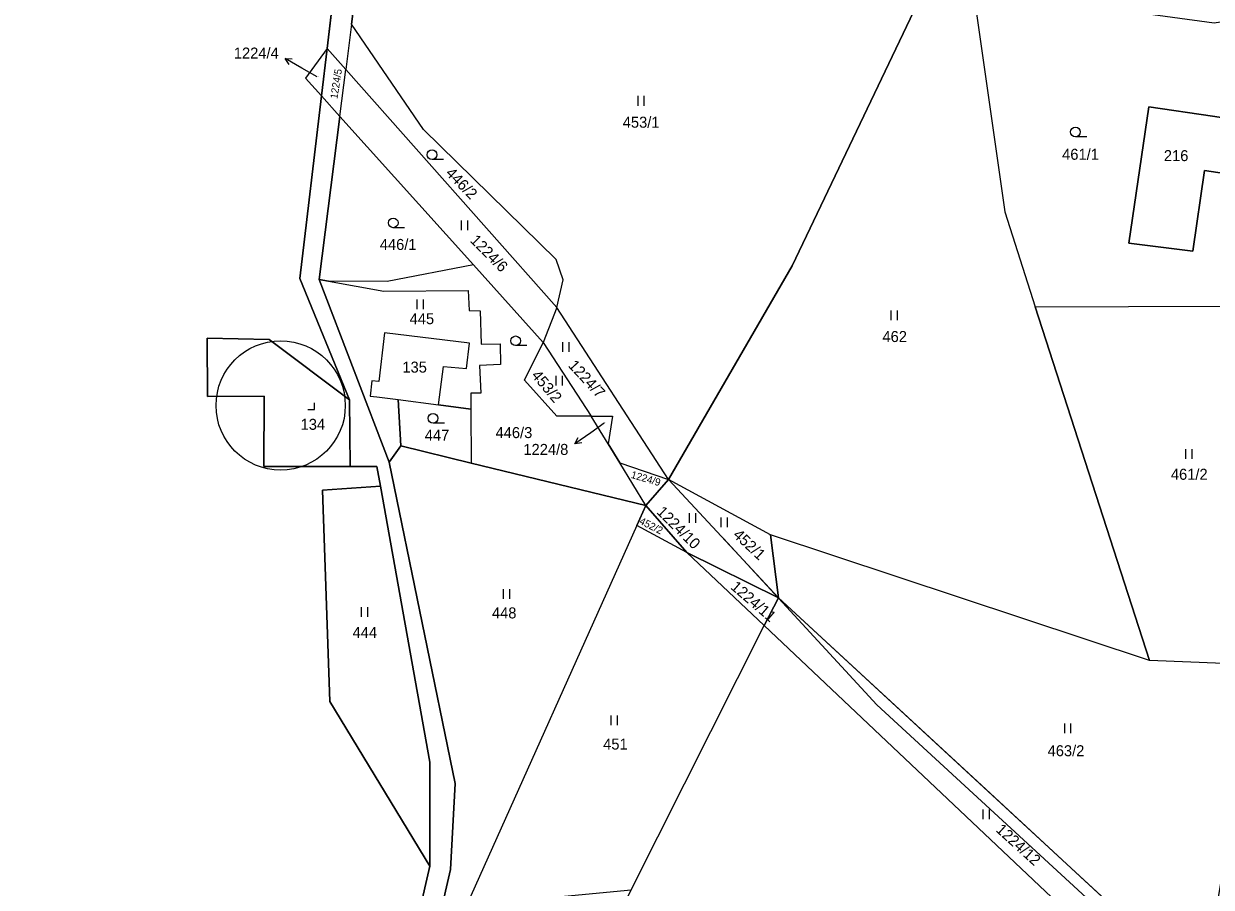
# Model space of a CAD drawing. Extents: x -588699 to -585793, y -1060280 to -1056731.
# Drawn here: x -587129.7 to -586946, y -1058770.6 to -1058637 of the extents above; entities that cross this region are included whole.
import ezdxf

# ---------------------------------------------------------------- set-up
doc = ezdxf.new("R2010")
doc.units = 0
for name, color, linetype in [('Druh pozemku', 7, 'Continuous'), ('Lesy', 7, 'Continuous'), ('Parcela nároku', 7, 'Continuous'), ('Parcelní číslo', 7, 'Continuous'), ('Stavby', 7, 'Continuous'), ('Vnější obvod_k šeření', 7, 'Continuous')]:
    doc.layers.add(name, color=color, linetype=linetype)

msp = doc.modelspace()

# ---------------------------------------------------------------- linework, layer by layer
at = {"layer": 'Druh pozemku'}
for p, q in [((-587034.74, -1058648.17), (-587034.74, -1058649.67)), ((-587033.71, -1058649.67), (-587033.71, -1058648.17)), ((-586965.26, -1058654.48), (-586967.01, -1058654.48)), ((-587064.8, -1058658), (-587066.55, -1058658)), ((-587062.05, -1058667.43), (-587062.05, -1058668.93)), ((-587061.03, -1058668.93), (-587061.03, -1058667.43)), ((-587070.81, -1058668.55), (-587072.56, -1058668.55)), ((-587068.92, -1058679.65), (-587068.92, -1058681.15)), ((-587067.9, -1058681.15), (-587067.9, -1058679.65)), ((-586995.56, -1058681.38), (-586995.56, -1058682.88)), ((-586994.54, -1058682.88), (-586994.54, -1058681.38)), ((-587051.87, -1058686.8), (-587053.62, -1058686.8)), ((-587046.36, -1058686.24), (-587046.36, -1058687.74)), ((-587045.33, -1058687.74), (-587045.33, -1058686.24)), ((-587047.38, -1058691.46), (-587047.38, -1058692.96)), ((-587046.35, -1058692.96), (-587046.35, -1058691.46)), ((-587064.65, -1058698.79), (-587066.4, -1058698.79)), ((-586949.96, -1058702.82), (-586949.96, -1058704.32)), ((-586948.94, -1058704.32), (-586948.94, -1058702.82)), ((-587026.78, -1058712.69), (-587026.78, -1058714.19)), ((-587025.76, -1058714.19), (-587025.76, -1058712.69)), ((-587021.87, -1058713.38), (-587021.87, -1058714.88)), ((-587020.84, -1058714.88), (-587020.84, -1058713.38)), ((-587055.54, -1058724.49), (-587055.54, -1058725.99)), ((-587054.52, -1058725.99), (-587054.52, -1058724.49)), ((-587077.52, -1058727.27), (-587077.52, -1058728.77)), ((-587076.49, -1058728.77), (-587076.49, -1058727.27)), ((-587038.9, -1058744.02), (-587038.9, -1058745.52)), ((-587037.88, -1058745.52), (-587037.88, -1058744.02)), ((-586968.72, -1058745.27), (-586968.72, -1058746.77)), ((-586967.7, -1058746.77), (-586967.7, -1058745.27)), ((-586981.34, -1058758.54), (-586981.34, -1058760.04)), ((-586980.32, -1058760.04), (-586980.32, -1058758.54))]:
    msp.add_line(p, q, dxfattribs=at)
msp.add_lwpolyline([(-587085.76, -1058696.66), (-587084.76, -1058696.66), (-587084.76, -1058695.66)], dxfattribs=at)
for centre in [(-586967.01, -1058653.73), (-587066.55, -1058657.25), (-587072.56, -1058667.8), (-587053.62, -1058686.05), (-587066.4, -1058698.04)]:
    msp.add_circle(centre, 0.75, dxfattribs=at)
at = {"layer": 'Lesy'}
for p, q in [((-587082.77, -1058640.81), (-587081.62, -1058631.18)), ((-587079.89, -1058644.06), (-587082.77, -1058640.81)), ((-587080.81, -1058651.32), (-587079.89, -1058644.06)), ((-587084.01, -1058676.54), (-587080.81, -1058651.32)), ((-587073.2, -1058704.82), (-587084.01, -1058676.54)), ((-587071.38, -1058702.32), (-587073.2, -1058704.82)), ((-587060.49, -1058704.96), (-587071.38, -1058702.32)), ((-587033.48, -1058711.51), (-587060.49, -1058704.96)), ((-587029.95, -1058707.51), (-587033.48, -1058711.51)), ((-587012.97, -1058725.79), (-587029.95, -1058707.51)), ((-586980.88, -1058755.42), (-587012.97, -1058725.79)), ((-586948.79, -1058785.05), (-586980.88, -1058755.42))]:
    msp.add_line(p, q, dxfattribs=at)
at = {"layer": 'Parcela nároku'}
for points in [[(-587082.77, -1058640.81), (-587081.62, -1058631.18), (-587082.04, -1058616.39), (-587089.34, -1058602.34), (-587092.39, -1058597.59), (-587095.99, -1058591.99), (-587093.17, -1058592.2), (-587086.6, -1058600.68), (-587081.74, -1058610.11), (-587078.73, -1058615.94), (-587078.34, -1058619.18), (-587077.6, -1058628.08), (-587078.23, -1058630.94), (-587079.01, -1058637.07), (-587079.89, -1058644.06)], [(-587079.01, -1058637.07), (-587078.23, -1058630.94), (-587027.45, -1058629.2), (-586988.17, -1058626.9), (-587010.84, -1058674.44), (-587029.95, -1058707.51), (-587047.27, -1058680.89), (-587046.25, -1058676.64), (-587047.36, -1058673.49), (-587067.87, -1058653.34)], [(-586988.17, -1058626.9), (-586973.23, -1058633.1), (-586982.68, -1058632.84), (-586977.96, -1058666.11), (-586973.22, -1058680.8), (-586955.56, -1058735.53), (-587014.17, -1058716.09), (-587029.95, -1058707.51), (-587010.84, -1058674.44)], [(-586932.16, -1058655.81), (-586936.67, -1058654.08), (-586933.73, -1058645.96), (-586930.55, -1058647.2), (-586927.38, -1058634.01), (-586945.54, -1058636.92), (-586973.23, -1058633.1), (-586982.68, -1058632.84), (-586977.96, -1058666.11), (-586973.22, -1058680.8), (-586929.95, -1058680.64), (-586929.59, -1058679.33), (-586933.94, -1058678.03)], [(-587067.87, -1058653.34), (-587079.01, -1058637.07), (-587079.89, -1058644.06), (-587047.27, -1058680.89), (-587046.25, -1058676.64), (-587047.36, -1058673.49)], [(-587082.77, -1058640.81), (-587086.11, -1058645.42), (-587083.65, -1058648.16)], [(-587079.89, -1058644.06), (-587082.77, -1058640.81), (-587083.65, -1058648.16), (-587080.81, -1058651.32)], [(-587080.81, -1058651.32), (-587079.89, -1058644.06), (-587047.27, -1058680.89), (-587049.34, -1058686.33), (-587060.15, -1058674.31)], [(-586945.81, -1058651.29), (-586941.68, -1058651.91), (-586942.92, -1058660.31), (-586947.04, -1058659.71), (-586948.86, -1058672.19), (-586958.77, -1058670.94), (-586955.67, -1058649.84)], [(-586958.77, -1058670.94), (-586948.86, -1058672.19), (-586947.04, -1058659.71), (-586942.92, -1058660.31), (-586941.68, -1058651.91), (-586945.81, -1058651.29), (-586955.67, -1058649.84)], [(-587080.81, -1058651.32), (-587060.15, -1058674.31), (-587073.49, -1058676.85), (-587082.55, -1058676.8), (-587084.01, -1058676.54)], [(-587073.49, -1058676.85), (-587082.55, -1058676.8), (-587074, -1058678.35), (-587060.98, -1058678.24), (-587060.81, -1058681.36), (-587059.09, -1058681.39), (-587058.97, -1058686.57), (-587056.02, -1058686.51), (-587055.96, -1058689.7), (-587059.21, -1058689.85), (-587058.98, -1058694.14), (-587060.57, -1058694.14), (-587060.55, -1058696.65), (-587060.49, -1058704.96), (-587033.48, -1058711.51), (-587037.52, -1058704.92), (-587039.31, -1058702), (-587041.95, -1058697.7), (-587047.24, -1058697.69), (-587052.26, -1058692.13), (-587049.34, -1058686.33), (-587060.15, -1058674.31)], [(-587075.07, -1058694.71), (-587071.77, -1058695.15), (-587071.38, -1058702.32), (-587073.2, -1058704.82), (-587084.01, -1058676.54), (-587082.55, -1058676.8), (-587074, -1058678.35), (-587060.98, -1058678.24), (-587060.81, -1058681.36), (-587059.09, -1058681.39), (-587058.97, -1058686.57), (-587056.02, -1058686.51), (-587055.96, -1058689.7), (-587059.21, -1058689.85), (-587058.98, -1058694.14), (-587060.57, -1058694.14), (-587060.55, -1058696.65), (-587065.54, -1058695.97), (-587064.79, -1058690), (-587061.24, -1058690.33), (-587060.77, -1058686.4), (-587073.89, -1058684.82), (-587074.8, -1058692.36), (-587075.86, -1058692.23), (-587076.15, -1058694.63)], [(-587029.95, -1058707.51), (-587047.27, -1058680.89), (-587049.34, -1058686.33), (-587041.95, -1058697.7), (-587038.65, -1058697.7), (-587039.31, -1058702), (-587037.52, -1058704.92)], [(-586973.22, -1058680.8), (-586929.95, -1058680.64), (-586935.97, -1058702.25), (-586938.93, -1058736.17), (-586955.56, -1058735.53)], [(-587091.76, -1058685.84), (-587079.33, -1058695.16), (-587079.21, -1058705.5), (-587092.6, -1058705.5), (-587092.52, -1058694.6), (-587101.31, -1058694.64), (-587101.33, -1058685.65)], [(-587073.89, -1058684.82), (-587074.8, -1058692.36), (-587075.86, -1058692.23), (-587076.15, -1058694.63), (-587075.07, -1058694.71), (-587071.77, -1058695.15), (-587065.54, -1058695.97), (-587064.79, -1058690), (-587061.24, -1058690.33), (-587060.77, -1058686.4)], [(-587049.34, -1058686.33), (-587041.95, -1058697.7), (-587047.24, -1058697.69), (-587052.26, -1058692.13)], [(-587065.54, -1058695.97), (-587060.55, -1058696.65), (-587060.49, -1058704.96), (-587071.38, -1058702.32), (-587071.77, -1058695.15)], [(-587041.95, -1058697.7), (-587038.65, -1058697.7), (-587039.31, -1058702)], [(-587068.95, -1058790.69), (-587063.69, -1058767.86), (-587062.95, -1058754.55), (-587073.2, -1058704.82), (-587071.38, -1058702.32), (-587060.49, -1058704.96), (-587033.48, -1058711.51), (-587034.88, -1058714.63), (-587061.22, -1058773.43)], [(-587037.52, -1058704.92), (-587029.95, -1058707.51), (-587033.48, -1058711.51)], [(-587033.48, -1058711.51), (-587029.95, -1058707.51), (-587012.97, -1058725.79), (-587027.13, -1058718.82)], [(-587012.97, -1058725.79), (-587014.17, -1058716.09), (-587029.95, -1058707.51)], [(-587074.55, -1058708.53), (-587066.87, -1058751.26), (-587066.87, -1058767.35), (-587082.35, -1058741.85), (-587083.48, -1058709.16)], [(-587034.88, -1058714.63), (-587033.48, -1058711.51), (-587027.13, -1058718.82)], [(-587027.13, -1058718.82), (-587034.88, -1058714.63), (-587061.22, -1058773.43), (-587035.75, -1058770.98), (-587015.18, -1058730.11)], [(-586955.56, -1058735.53), (-587014.17, -1058716.09), (-587012.97, -1058725.79), (-586948.79, -1058785.05), (-586945.33, -1058774.96), (-586938.93, -1058736.17)], [(-587027.13, -1058718.82), (-587012.97, -1058725.79), (-587015.18, -1058730.11)], [(-587012.97, -1058725.79), (-586948.79, -1058785.05), (-586950.81, -1058790.94), (-587015.18, -1058730.11)], [(-587049, -1058798.36), (-587035.75, -1058770.98), (-587015.18, -1058730.11), (-586950.81, -1058790.94), (-586952.1, -1058794.64), (-586956.26, -1058799.45), (-586977.77, -1058790.14), (-586983.47, -1058791.82), (-586986.93, -1058805.34), (-586975.35, -1058815.6), (-587001.81, -1058846.94), (-587015.61, -1058862.01), (-587018.01, -1058859.21), (-587014.91, -1058836.17), (-587030.43, -1058823.41), (-587054.26, -1058810.56)]]:
    msp.add_lwpolyline(points, close=True, dxfattribs=at)
for points in [[(-587140.01, -1058634.05), (-587129.38, -1058630.44), (-587121.34, -1058632.85), (-587097.69, -1058632.94), (-587081.62, -1058631.18), (-587082.77, -1058640.81), (-587086.11, -1058645.42), (-587083.65, -1058648.16), (-587087.01, -1058676.41), (-587079.33, -1058695.16), (-587091.76, -1058685.84), (-587101.33, -1058685.65), (-587101.31, -1058694.64), (-587092.52, -1058694.6), (-587092.6, -1058705.5), (-587079.21, -1058705.5), (-587075.09, -1058705.5), (-587074.55, -1058708.53), (-587083.48, -1058709.16), (-587082.35, -1058741.85), (-587066.87, -1058767.35), (-587071.99, -1058789.51), (-587095.97, -1058834.07), (-587178.54, -1058775.59)], [(-587154.97, -1058932.12), (-587114.84, -1058869.89), (-587097.12, -1058836.2), (-587095.97, -1058834.07), (-587071.99, -1058789.51), (-587066.87, -1058767.35), (-587066.87, -1058751.26), (-587074.55, -1058708.53), (-587075.09, -1058705.5), (-587079.21, -1058705.5), (-587079.33, -1058695.16), (-587087.01, -1058676.41), (-587083.65, -1058648.16), (-587080.81, -1058651.32), (-587084.01, -1058676.54), (-587073.2, -1058704.82), (-587062.95, -1058754.55), (-587063.69, -1058767.86), (-587068.95, -1058790.69), (-587112.04, -1058874.39), (-587151.08, -1058934.21)]]:
    msp.add_lwpolyline(points, dxfattribs=at)
at = {"layer": 'Parcelní číslo'}
for p, q in [((-587086.69, -1058643.87), (-587089.3, -1058642.38)), ((-587084.32, -1058645.22), (-587086.69, -1058643.87)), ((-587039.9, -1058698.78), (-587042.01, -1058700.27)), ((-587042.01, -1058700.27), (-587044.46, -1058702))]:
    msp.add_line(p, q, dxfattribs=at)
for points in [[(-587088.68, -1058643.31), (-587089.3, -1058642.38), (-587088.18, -1058642.44)], [(-587043.36, -1058701.83), (-587044.46, -1058702), (-587043.93, -1058701.02)]]:
    msp.add_lwpolyline(points, dxfattribs=at)
at = {"layer": 'Stavby'}
msp.add_circle((-587089.97, -1058696.05), 10, dxfattribs=at)
at = {"layer": 'Vnější obvod_k šeření'}
msp.add_lwpolyline([(-587021.46, -1058716.65), (-586997.74, -1058742.36), (-586940.72, -1058794.89), (-586902.9, -1058829.34), (-586866.18, -1058845.13), (-586845.7, -1058856.23), (-586823.14, -1058865.78), (-586804.29, -1058877.74), (-586768.37, -1058900.63), (-586740.68, -1058918.94), (-586706.93, -1058947.32), (-586695.04, -1058961.51), (-586665.86, -1059019.41), (-586658.31, -1059047.79), (-586653.05, -1059076.05), (-586647.1, -1059142.54), (-586641.38, -1059221.73), (-586641.38, -1059295.42)], dxfattribs=at)

# ---------------------------------------------------------------- texts
at = {"layer": 'Parcela nároku'}
for s, height, p in [('1224/4', 0.1, (-587084.52, -1058645.22)), ('453/1', 1.7, (-587037.05, -1058653.08)), ('461/1', 1.7, (-586969.07, -1058658.04)), ('216', 1.7, (-586953.33, -1058658.25)), ('446/1', 1.7, (-587074.64, -1058671.99)), ('445', 1.7, (-587070.02, -1058683.48)), ('462', 1.7, (-586996.87, -1058686.24)), ('135', 1.7, (-587071.14, -1058690.97)), ('134', 1.7, (-587086.89, -1058699.82)), ('1224/8', 0.1, (-587040.1, -1058698.78)), ('447', 1.7, (-587067.68, -1058701.5)), ('446/3', 1.7, (-587056.73, -1058701.1)), ('461/2', 1.7, (-586952.25, -1058707.55)), ('448', 1.7, (-587057.29, -1058729)), ('444', 1.7, (-587078.85, -1058732.02)), ('451', 1.7, (-587040.08, -1058749.29)), ('463/2', 1.7, (-586971.32, -1058750.32))]:
    msp.add_text(s, height=height, dxfattribs=at).set_placement(p)
for s, height, rotation, p in [('1224/5', 1.14, 81.0274, (-587081.2, -1058648.68)), ('446/2', 1.7, 314.162, (-587064.56, -1058660.22)), ('1224/6', 1.7, 315, (-587060.78, -1058670.64)), ('1224/7', 1.7, 312.847, (-587045.59, -1058689.96)), ('453/2', 1.7, 310.0859, (-587051.28, -1058691.45)), ('1224/9', 1.14, 343.706, (-587035.87, -1058707.24)), ('1224/10', 1.7, 315.4864, (-587031.93, -1058712.66)), ('452/2', 1.14, 333.28, (-587034.61, -1058714.31)), ('452/1', 1.7, 316.9423, (-587020.1, -1058716.24)), ('1224/11', 1.7, 319.3527, (-587020.48, -1058724.32)), ('1224/12', 1.7, 317.8272, (-586979.45, -1058761.86))]:
    msp.add_text(s, height=height, rotation=rotation, dxfattribs=at).set_placement(p)
at = {"layer": 'Parcelní číslo'}
for s, p in [('1224/4', (-587097.22, -1058642.38)), ('1224/8', (-587052.42, -1058703.7))]:
    msp.add_text(s, height=1.7, dxfattribs=at).set_placement(p)

doc.saveas('drawing.dxf')
